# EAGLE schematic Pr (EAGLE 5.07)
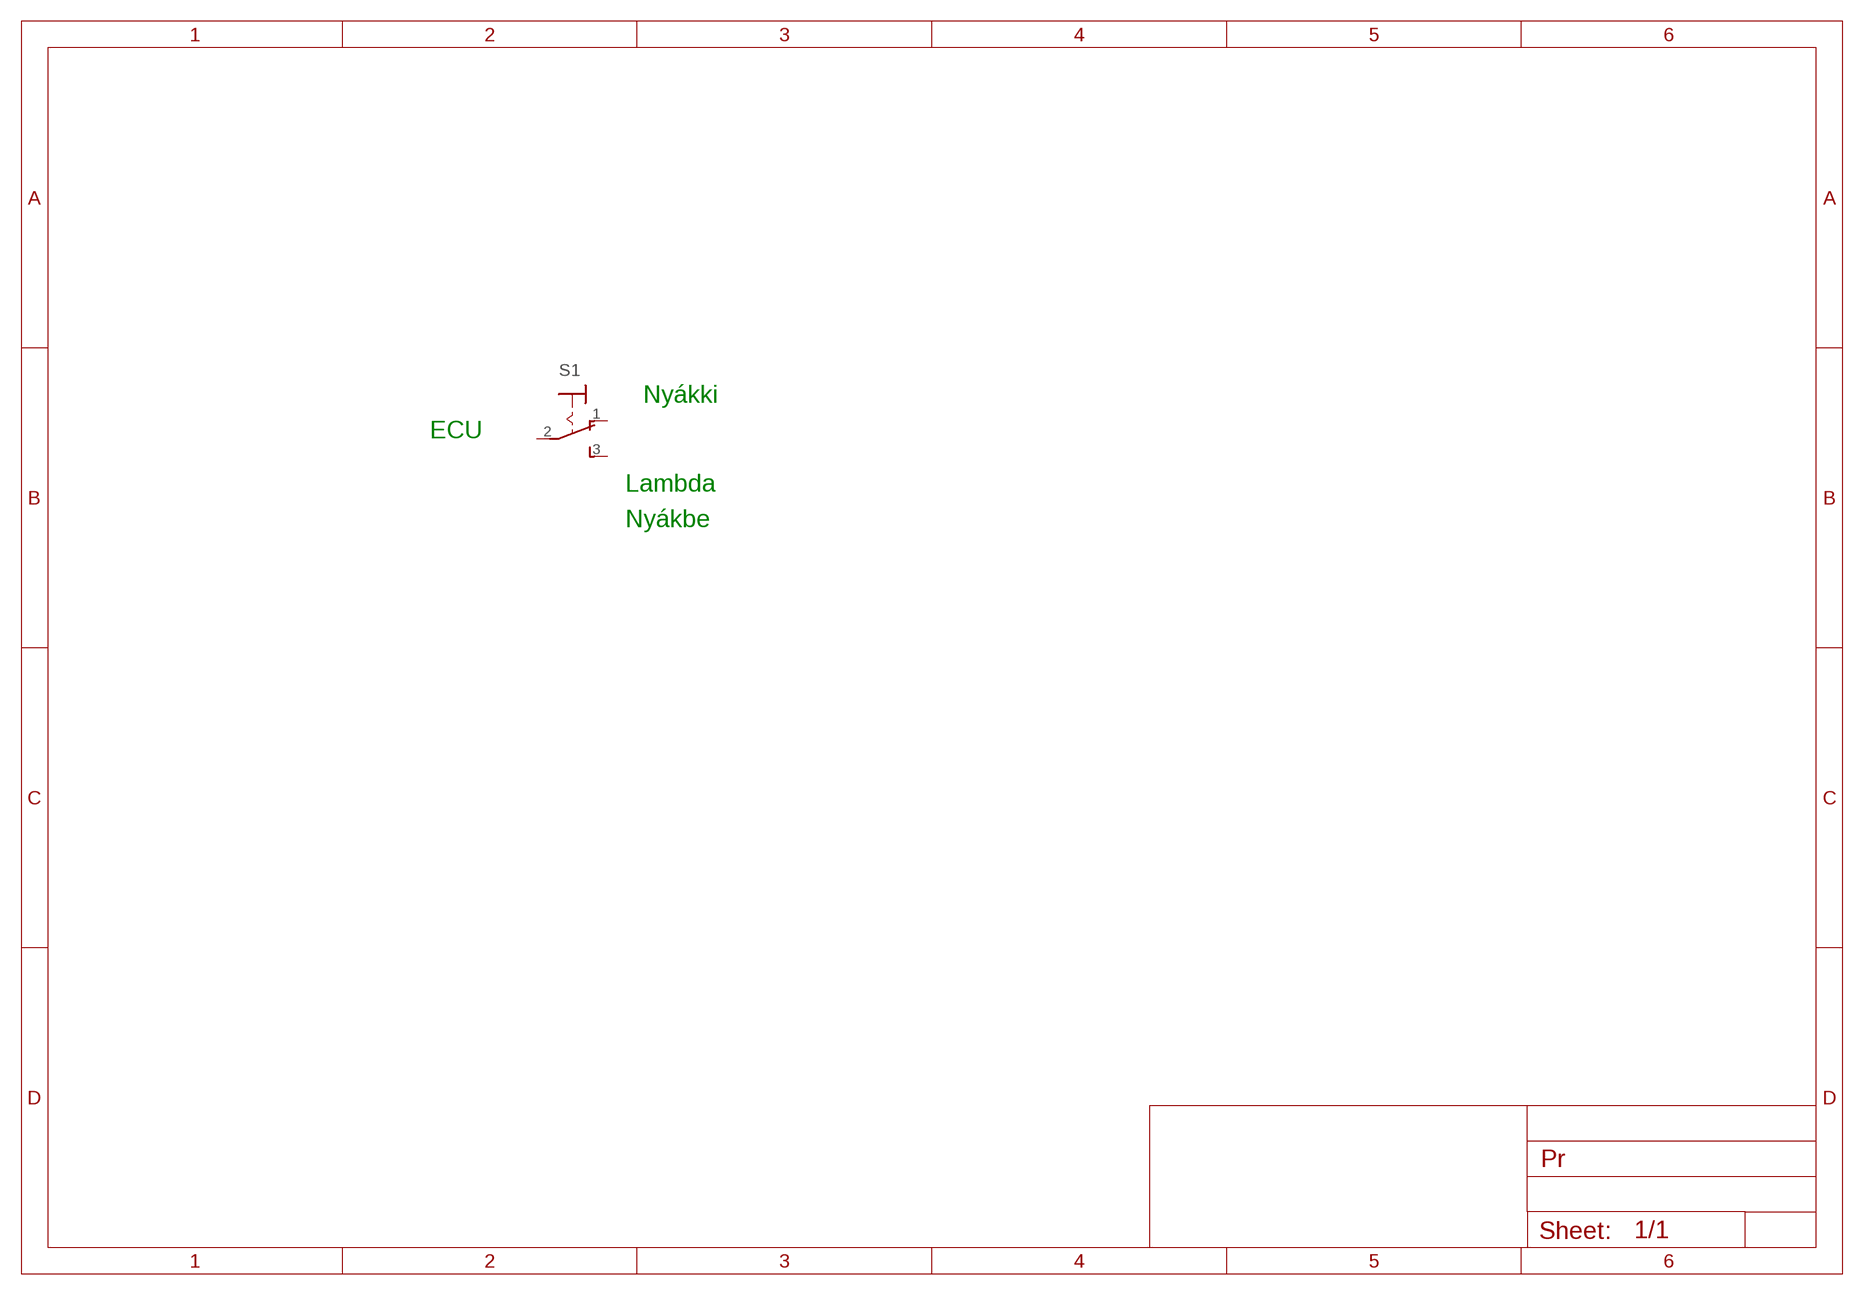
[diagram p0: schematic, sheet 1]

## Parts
S1  320-916  [320-916]
Unconnected: S1.1(O) S1.2(P) S1.3(S)

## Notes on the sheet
- Nyákki
- ECU
- Lambda
- Nyákbe

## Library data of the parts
S1 = switch:320-916: TOGGLE SWITCH distributor RS Components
